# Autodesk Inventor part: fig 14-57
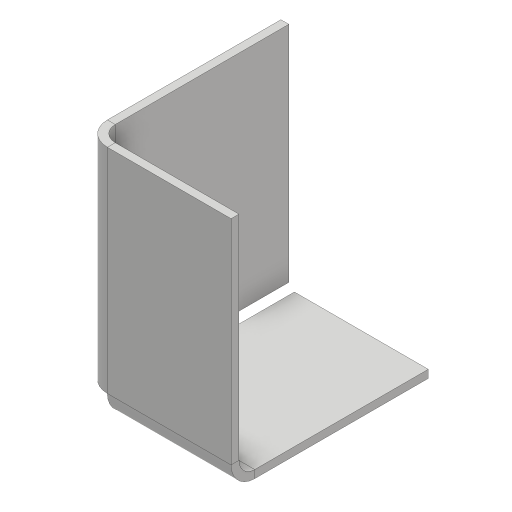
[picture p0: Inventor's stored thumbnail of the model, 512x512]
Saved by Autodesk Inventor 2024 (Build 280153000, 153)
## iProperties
Created: 2017-05
Part Number: fig 14-57
Material: Generic
Document SubType Name: Sheet Metal
Designer: CADCIM 00
Density: 1 g/cm^3
Sheet Metal Rule: Default_mm
Appearance: Default
Author: CADCIM 00
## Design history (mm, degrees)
node "Face1"
  sketch "Sketch1"
    geometry: L1 (0, 0)-(-15.678, 0); L2 (-15.678, 0)-(-15.678, -27.036); L3 (-15.678, -27.036)-(0, -27.036); L4 (0, -27.036)-(0, 0)
    constraints: 8 end point, 2 parallel, 1 horizontal, 1 perpendicular
node "Flange1"
body "Solid1"
face "Plate1" dims "d0" = 1 (= Thickness)
sketch "Sketch2"
  geometry: L1 (-22, 0)-(-22, -27.036); L2 (-22, -27.036)-(0, -27.036); 1 other entity
  constraints: 4 end point, 4 other
face "Plate2" dims "d0" = 1 (= Thickness), "d1" = 1 (= BendReliefWidth), "d2" = 0.5 (= BendReliefDepth), "d3" = 2 (= MinimumRemnant), "d4" = 2 (= TransitionRadius), "d5" = 25, "d6" = 90 deg, "d7" = 2 (= BendRadius), "d8" = 4 (= CornerReliefSize), "d9" = 1 (= GapSize), "d10" = 2 (= JacobiRadiusSize), "SeamGap" = 0.01
bend "Bend1" dims "d0" = 1 (= Thickness), "d1" = 1 (= BendReliefWidth), "d2" = 0.5 (= BendReliefDepth), "d3" = 2 (= MinimumRemnant), "d4" = 2 (= TransitionRadius), "d5" = 25, "d6" = 90 deg, "d7" = 2 (= BendRadius), "SeamGap" = 0.01
feature "Corner1" dims "d5" = 25, "d6" = 90 deg, "d8" = 4 (= CornerReliefSize), "d9" = 1 (= GapSize), "d10" = 2 (= JacobiRadiusSize)
other parameters: "Thickness" = 1 (derived), "BendRadius" = 2 (= 2 x Thickness), "BendReliefWidth" = 1 (= Thickness), "BendReliefDepth" = 0.5 (= 0.5 x Thickness), "CornerReliefSize" = 4 (= 4 x Thickness), "MinimumRemnant" = 2 (= 2 x Thickness), "TransitionRadius" = 2 (= BendRadius), "JacobiRadiusSize" = 2 (= BendRadius), "GapSize" = 1 (= Thickness)
